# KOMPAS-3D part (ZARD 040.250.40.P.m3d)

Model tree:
1. Булева операция:1
2. Булева операция:2
3. Булева операция:3
4. Булева операция:4
5. Булева операция:5
6. Булева операция:6
7. Булева операция:7
8. Булева операция:8
9. Булева операция:9
10. Булева операция:10
11. Булева операция:11
12. Булева операция:12
13. Булева операция:13
14. Булева операция:14
15. Булева операция:15
16. Булева операция:16
17. Булева операция:17
18. Булева операция:18
19. Булева операция:19
20. Булева операция:20
21. Булева операция:21
22. Булева операция:22

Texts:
  ООО ИК Энерпред-Ярдос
